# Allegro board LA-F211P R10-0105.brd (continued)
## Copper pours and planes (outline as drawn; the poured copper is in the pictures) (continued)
N25790 on BOTTOM (solid shape): 148.48,67.29 148.48,65.59 148.41,65.51 146.07,65.51 145.94,65.39 145.94,61.61 145.87,61.53 145.22,61.53 144.7,61 144.7,60 144.52,59.82 143.24,59.82 142.97,60.09 142.97,67.14 143.23,67.39 148.38,67.39
N25900 on BOTTOM (solid shape): 148,64.64 148,63.73 147.72,63.46 147.72,62.08 147.65,62.01 147.29,62.01 147.21,62.08 147.21,63.56 147.39,63.73 147.65,63.73 147.77,63.86 147.77,64.63 147.83,64.69 147.95,64.69
N25968 on BOTTOM (solid shape): 147.6,63.89 147.24,63.89 146.91,63.56 146.91,61.57 146.85,61.51 146.4,61.51 146.34,61.58 146.34,64.15 146.88,64.7 147.6,64.7
N29706 on BOTTOM (solid shape): 111.92,43.29 111.92,40.7 111.63,40.41 111.02,40.41 110.81,40.2 110.81,39.92 110.46,39.58 110.46,39.12 110.21,38.87 110.21,37.19 110.13,37.12 108.4,37.12 108.33,37.19 108.33,39.43 107.9,39.86 105.51,39.86 105.46,39.91 105.46,40.44 106.22,41.2 106.22,43.15 106.75,43.68 111.53,43.68
N54708 on BOTTOM (solid shape): 145.28,57.61 147.95,57.61 148.03,57.54 148.03,55.84 147.95,55.76 145.67,55.76 145.31,55.4 145.31,51.75 145.52,51.54 145.52,50.85 145.43,50.76 143.98,50.76 142.8,51.95 142.8,57.83 142.92,57.95 142.92,58.17 143.23,58.48 144.42,58.48
N54789 on TOP (solid shape): 115.27,43.35 115.28,43.35 115.38,43.25 115.38,40.58 115.18,40.37 112.51,40.37 112.35,40.53 112.35,43.07 112.78,43.5 115.12,43.5
N54789 on BOTTOM (solid shape): 119.47,43.62 119.47,40.52 119.16,40.2 117.9,40.2 117.71,40.01 117.71,38.49 117.07,37.85 117.07,36.23 116.99,36.15 115.24,36.15 115.19,36.2 115.19,38.72 114.96,38.94 113.1,38.94 113.01,38.86 112.35,38.86 112.3,38.91 112.3,43.03 113.1,43.82 119.26,43.82
N54830 on TOP (solid shape): 123.23,43.68 123.23,41.2 122.98,40.95 119.94,40.95 119.8,41.09 119.8,43.27 120.27,43.74 123.17,43.74
N54830 on BOTTOM (solid shape): 127.01,43.57 127.01,40.08 126.62,39.68 125.63,39.68 125.41,39.47 125.41,39.22 124.71,38.51 124.71,37.83 124.3,37.42 124.3,35.82 124.23,35.74 122.5,35.74 122.42,35.82 122.42,38.26 122.25,38.44 121.59,38.44 121.18,38.84 119.89,38.84 119.8,38.93 119.8,39.95 119.81,39.96 119.81,43.25 120.27,43.71 126.88,43.71
N19473637 on TOP (solid shape): 84.68,107.91 86.33,107.91 86.46,107.78 86.46,105.75 86.23,105.52 85.41,105.52 85.38,105.49 83.23,105.49 83.13,105.59 83.13,106.04 83.28,106.2 83.28,108.29 83.41,108.41 84.17,108.41
N46643804 on BOTTOM (solid shape): 114.37,37.9 114.37,37.06 113.59,37.06 113.59,37.7 113.36,37.93 112.35,37.93 112.3,37.98 112.3,38.55 112.39,38.64 113.64,38.64
N46645235 on BOTTOM (solid shape): 121.61,37.9 121.61,36.66 120.82,36.66 120.82,37.6 120.52,37.9 119.87,37.9 119.78,37.99 119.78,38.41 119.87,38.49 121.02,38.49
N46648066 on BOTTOM (solid shape): 147.55,54.9 147.55,53.98 147.04,53.47 147.04,52.13 146.94,52.03 146.58,52.03 146.45,52.15 146.45,53.6 146.83,53.98 147.16,53.98 147.32,54.13 147.32,54.9 147.37,54.95 147.49,54.95
N46648174 on BOTTOM (solid shape): 147.14,54.13 146.61,54.13 146.28,53.8 146.28,51.81 146.43,51.65 146.43,50.85 146.37,50.78 145.71,50.78 145.64,50.85 145.64,54.13 146.45,54.95 147.14,54.95
N46648510 on BOTTOM (solid shape): 107.32,39.5 107.32,39.01 107.51,38.82 107.51,38 106.73,38 106.7,38.03 106.7,38.46 106.19,38.98 105.49,38.98 105.44,39.02 105.44,39.53 105.62,39.71 107.12,39.71
N55155823 on TOP (solid shape): 62.46,99.9 62.46,99.52 62.96,99.02 63.6,99.02 63.85,98.76 63.85,98.13 64.04,97.94 64.04,96.95 63.82,96.73 62.17,96.73 61.82,97.08 61.82,99.9 61.95,100.03 62.33,100.03
N55155827 on TOP (solid shape): 63.99,96.37 64.59,95.62 65.33,96.23 66.09,96.23 66.19,96.14 66.19,95.33 66.32,95.2 66.32,94.54 66.22,94.44 64.82,94.44 64.67,94.29 63.47,94.29 63.32,94.44 60.21,94.44 59.85,94.8 59.85,96.3 59.97,96.41 63.95,96.41
N120361841 on BOTTOM (solid shape): 21.69,33.29 21.74,33.24 21.74,31.98 21.66,31.91 21.54,31.91 21.48,31.96 21.48,32.62 21.38,32.72 21.31,32.72 21.26,32.67 21.26,31.98 21.18,31.91 21.05,31.91 20.98,31.98 20.98,32.72 20.93,32.77 20.93,34.18 20.93,34.18 21.69,34.18
N122755391 on BOTTOM (solid shape): 84.16,27.45 84.16,27.21 84.34,27.03 85.26,27.03 85.32,26.98 85.32,26.09 85.06,25.84 82.14,25.84 81.99,25.99 81.99,27.31 82.17,27.49 84.12,27.49
N122912247 on TOP (solid shape): 112.77,29.93 112.77,28.71 112.99,28.49 112.99,27.67 113.24,27.43 113.24,26.7 113.17,26.63 111.76,26.63 111.65,26.73 111.65,29.99 111.8,30.13 112.57,30.13
N125857121 on BOTTOM (solid shape): 65.76,89.9 65.76,87.97 65.38,87.59 63.23,87.59 63.11,87.71 63.11,89.56 63.27,89.72 64.16,89.72 64.16,89.99 64.27,90.11 65.55,90.11
N125861425 on TOP (solid shape): 149.51,103.59 149.85,103.47 150.03,103.16 150.03,102.49 149.96,102.31 149.83,102.16 149.64,101.98 146.9,101.98 146.88,102 146.88,103.35 146.96,103.44 147.65,103.44 147.8,103.59
N127291517 on BOTTOM (solid shape): 56.42,102.13 56.42,101.24 56.23,101.05 55.44,101.05 55.06,101.42 54.08,101.42 53.95,101.56 53.95,102.06 54.07,102.19 56.36,102.19
N132640228 on BOTTOM (solid shape): 163.93,13.17 163.93,12.47 163.85,12.39 163.02,12.39 162.76,12.13 162.76,11.49 162.68,11.41 161.94,11.41 161.88,11.47 161.88,12.42 162.03,12.57 162.16,12.57 162.33,12.74 162.33,12.87 162.68,13.22 163.88,13.22
N132938389 on BOTTOM (solid shape): 60.02,80.78 59.97,80.73 59.08,80.73 58.92,80.88 57.71,80.88 57.71,81.13 57.78,81.21 59.1,81.21 59.36,81.46 60.02,81.46
N132946479 on BOTTOM (solid shape): 13.43,23.58 12.93,23.58 12.8,23.7 11.27,23.7 11.15,23.83 11.15,23.96 11.27,24.09 13.43,24.09
N132946567 on BOTTOM (solid shape): 13.94,24.72 14.58,24.72 14.7,24.59 14.7,23.83 14.58,23.7 13.94,23.7 13.81,23.83 13.81,24.09 13.56,24.34 10.89,24.34 10.89,23.96 10.77,23.83 10.64,23.83 10.51,23.96 10.51,24.59 11.02,25.1 13.56,25.1
N132946609 on BOTTOM (solid shape): 59.86,81.82 59.84,81.79 59.77,81.79 59.75,81.81 59.19,81.81 58.85,81.46 57.55,81.46 57.45,81.36 57.45,81.06 57.27,80.88 57.04,80.88 56.97,80.96 56.97,81.87 57.67,82.57 59.12,82.57 59.25,82.71 59.86,82.71
N133127797 on TOP (solid shape): 68.42,101.49 67.79,100.86 66.07,100.86 66.01,100.92 66.01,101.94 66.14,102.06 68.42,102.06
N133127913 on TOP (solid shape): 65.69,105.11 64.8,104.22 64.55,104.22 64.55,105.05 65,105.49 65,106.19 65.12,106.32 65.69,106.32
N133127941 on TOP (solid shape): 66.96,105.07 65.36,103.47 64.61,103.47 64.55,103.53 64.55,103.97 64.61,104.03 64.93,104.03 66.07,105.17 66.07,105.75 66.96,105.75
N137153201 on BOTTOM (solid shape): 47.02,70.5 47.02,69.02 47.09,68.95 47.09,67.77 46.83,67.52 46.33,67.52 46.2,67.65 46.2,68.71 46.2,68.72 46.21,68.89 46.1,69.02 46.07,69.04 46.07,69.81 45.95,69.93 45.31,69.93 45.18,70.06 45.18,70.57 45.31,70.69 46.83,70.69
N140304666 on TOP (solid shape): 60.17,52.09 60.17,50.12 60.04,49.99 59.22,49.99 59.15,50.06 59.15,51.07 58.39,51.83 58.39,52.47 58.52,52.6 59.66,52.6
N142919801 on BOTTOM (solid shape): 82.69,22.27 84.12,22.27 84.17,22.22 84.17,20.77 83.97,20.57 81.46,20.57 81.31,20.73 81.31,21.38 81.12,21.56 81.12,22.43 81.25,22.56 82.39,22.56
N143012284 on BOTTOM (solid shape): 153.51,5.29 153.51,3.51 152.57,2.57 152.56,2.57 152.51,2.51 152.13,2.51 152.07,2.58 151.75,2.58 151.65,2.48 151.03,2.48 151,2.44 151,1.79 150.81,1.61 147.93,1.61 147.8,1.73 147.8,2.43 148.5,2.43 148.75,2.69 148.75,2.94 148.5,3.19 147.8,3.19 147.8,3.77 147.93,3.89 148.75,3.89 148.93,4.07 148.93,4.07 150.47,5.61 153.2,5.61
N146334871 on BOTTOM (solid shape): 93.95,28.56 93.95,27.77 93.85,27.67 91.54,27.67 91.53,27.68 91.53,28.62 91.56,28.66 93.85,28.66
N146336831 on TOP (solid shape): 27.75,29.98 27.75,28.53 27.67,28.45 26.84,28.45 26.67,28.63 25.4,28.63 25.29,28.73 25.29,28.83 25.37,28.91 26.06,28.91 26.13,28.99 26.13,29.09 26.08,29.14 25.4,29.14 25.29,29.24 25.29,29.5 25.45,29.65 26.46,29.65 26.87,30.05 27.67,30.05
N146979809 on TOP: 68.07,87.68 69.36,87.68 69.86,88.19 69.86,89.22 69.31,89.77 68.41,89.77 68.34,89.71 68.34,89.12 68.01,88.79 68.01,87.74
N146979833 on TOP: 65.21,87.7 64.9,88 64.9,88.66 65.33,89.09 65.33,89.71 65.42,89.8 66.23,89.8 66.34,89.69 66.34,89.12 66.66,88.8 66.66,87.76 66.59,87.7
N146979907 on BOTTOM (solid shape): 60.73,72.52 60.73,70.81 60.65,70.73 59.62,70.73 59.43,70.55 57.35,70.55 57.29,70.61 57.29,71.28 57.4,71.39 58.36,71.39 58.7,71.73 59.6,71.73 59.7,71.83 59.7,72.58 59.77,72.65 60.6,72.65
N148592439 on BOTTOM (solid shape): 88.11,34.09 88.11,32.38 87.88,32.15 86.99,32.15 86.93,32.21 86.93,32.91 87.21,33.19 87.44,33.19 87.75,33.5 87.75,34.1 87.84,34.19 88.01,34.19
N148592442 on BOTTOM (solid shape): 87.95,31.5 87.95,30.8 87.87,30.72 85.51,30.72 85.41,30.82 85.41,31.47 85.5,31.56 87.89,31.56
N148592463 on BOTTOM (solid shape): 87.09,34.12 87.09,33.24 86.6,32.75 86.6,32.21 86.5,32.11 85.47,32.11 85.39,32.19 85.39,33.03 85.54,33.17 86.37,33.17 86.75,33.55 86.75,34.11 86.85,34.21 87.01,34.21
N148593135 on BOTTOM (solid shape): 89.08,34.11 89.08,33.13 89.32,32.88 89.32,32.26 89.72,31.87 90.27,31.87 90.57,31.58 90.57,30.82 90.46,30.71 89.5,30.71 89.37,30.84 89.37,31.52 89.18,31.72 88.39,31.72 88.29,31.82 88.29,32.99 88.76,33.46 88.76,34.11 88.85,34.2 88.99,34.2
N148597432 on BOTTOM (solid shape): 70.78,34.15 70.78,32.35 70.64,32.2 69.49,32.2 69.47,32.22 69.47,32.86 69.64,33.03 69.98,33.03 70.44,33.48 70.44,34.14 70.49,34.2 70.73,34.2
N148597434 on BOTTOM (solid shape): 70.49,31.54 70.49,30.77 70.38,30.66 68.19,30.66 68.1,30.75 68.1,31.54 68.21,31.65 70.38,31.65
N148597440 on BOTTOM (solid shape): 69.78,34.13 69.78,33.36 69.21,32.79 69.21,32.28 69.1,32.17 68.19,32.17 68.16,32.2 68.16,32.91 68.28,33.03 68.93,33.03 69.44,33.54 69.44,34.13 69.5,34.2 69.72,34.2
N148597468 on BOTTOM (solid shape): 71.77,34.13 71.77,33.27 72.04,33 72.04,32.25 72.31,31.99 73.14,31.99 73.33,31.8 73.33,30.79 73.25,30.71 72.17,30.71 72.09,30.78 72.09,31.54 71.97,31.66 71.07,31.66 70.96,31.78 70.96,32.97 71.45,33.47 71.45,33.85 71.45,33.85 71.45,34.15 71.5,34.2 71.7,34.2
N148599110 on BOTTOM (solid shape): 79.36,34.12 79.36,32.41 79.13,32.17 78.24,32.17 78.18,32.23 78.18,32.85 78.54,33.21 78.69,33.21 79,33.53 79,34.13 79.09,34.22 79.26,34.22
N148599112 on BOTTOM (solid shape): 79.19,31.54 79.19,30.82 79.09,30.71 76.9,30.71 76.78,30.83 76.78,31.54 76.84,31.6 79.14,31.6
N148599118 on BOTTOM (solid shape): 78.34,34.14 78.34,33.21 77.85,32.72 77.85,32.23 77.75,32.13 76.8,32.13 76.77,32.16 76.77,33.09 76.88,33.2 77.66,33.2 78,33.54 78,34.13 78.1,34.23 78.26,34.23
N148599146 on BOTTOM (solid shape): 80.33,34.14 80.33,33.15 80.57,32.91 80.57,32.16 80.83,31.9 81.52,31.9 81.82,31.6 81.82,30.84 81.71,30.74 80.75,30.74 80.62,30.87 80.62,31.51 80.39,31.74 79.64,31.74 79.54,31.85 79.54,33.01 80.01,33.48 80.01,34.13 80.1,34.22 80.24,34.22
N148600854 on BOTTOM (solid shape): 96.95,34.11 96.95,33.26 96.58,32.89 96.58,32.24 96.45,32.11 95.59,32.11 95.53,32.17 95.53,32.84 95.89,33.2 96.05,33.2 96.05,33.2 96.28,33.2 96.59,33.51 96.59,34.12 96.68,34.21 96.85,34.21
N148600856 on BOTTOM (solid shape): 96.52,31.44 96.52,30.79 96.44,30.71 94.11,30.71 94.04,30.78 94.04,31.41 94.13,31.5 96.47,31.5
N148600862 on BOTTOM (solid shape): 95.93,34.13 95.93,33.41 95.38,32.86 95.38,32.16 95.34,32.12 94.16,32.12 94.11,32.17 94.11,33.03 94.26,33.18 95.21,33.18 95.59,33.56 95.59,34.12 95.69,34.22 95.85,34.22
N148600909 on BOTTOM (solid shape): 97.91,34.13 97.91,32.15 98.18,31.89 98.99,31.89 99.1,31.77 99.1,30.8 99.03,30.72 98,30.72 97.95,30.78 97.95,31.38 97.68,31.65 97.11,31.65 96.83,31.92 96.83,32.86 96.97,33 97.13,33 97.6,33.47 97.6,34.12 97.69,34.21 97.83,34.21
N150849033 on TOP (solid shape): 158.36,21.8 158.36,20.87 157.46,19.97 157.46,19.52 157.4,19.45 156.81,19.45 156.28,19.99 156.28,20.22 156.22,20.28 156.22,21.38 156.26,21.42 156.97,21.42 157.6,22.05 158.11,22.05
N151224429 on TOP (solid shape): 62.15,75.24 62.15,74.76 62.55,74.37 62.55,73.53 61.91,72.88 59.92,72.88 59.74,73.06 59.74,74.04 59.8,74.1 61.27,74.1 61.59,74.42 61.59,75.25 61.69,75.34 62.05,75.34
N151224640 on TOP (solid shape): 59.61,75.27 59.61,73.39 59.19,72.97 56.04,72.97 55.91,73.1 55.91,73.81 56.27,74.17 58.67,74.17 59.1,74.59 59.1,75.23 59.2,75.33 59.55,75.33
N151224855 on TOP (solid shape): 50.28,54.76 50.28,53.46 50.09,53.27 49.3,53.27 49.29,53.28 48.69,53.28 48.55,53.42 48.55,54.6 49.02,55.07 49.97,55.07
N153659070 on BOTTOM (solid shape): 5.03,9.2 6.56,9.2 6.72,9.04 6.72,7.98 6.66,7.91 4.75,7.91 4.11,8.55 3.36,8.55 3.16,8.75 3.16,9.75 3.33,9.92 4.32,9.92
N154411599 on TOP (solid shape): 120.01,20.58 120.01,19.45 119.9,19.34 118.68,19.34 118.59,19.43 116.64,19.43 116.56,19.51 116.56,20.48 116.73,20.66 119.94,20.66
N154411647 on TOP (solid shape): 121.89,20.07 121.89,19.46 121.74,19.31 120.22,19.31 120.12,19.42 120.12,20.17 120.22,20.28 121.69,20.28
N154450732 on TOP (solid shape): 142.56,85.5 142.56,81.97 142.42,81.83 141.88,81.83 141.75,81.96 141.75,85.46 141.83,85.54 142.52,85.54
N154450766 on TOP (solid shape): 141.54,82.36 141.54,81.77 141.16,81.39 139.94,81.39 139.86,81.47 139.86,82.13 139.98,82.26 140.77,82.26 140.91,82.4 141.5,82.4

Small or netless copper shapes (teardrops, artwork), in the pictures only: 47 on TOP, 40 on BOTTOM, 4 on IN1, 128 on GND2, 270 on GND3, 1 on GND4

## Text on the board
Ref Des/Silkscreen Bottom: H5 | H27 | S1 | H4 | S2 | OFF | ON
User.Comments: LAF211P | 2019-01-05 | 2018-01-05 | DAZ10 | crazy | 1.0(A00)
Ref Des/Silkscreen Top: S3 | H52 | H51
GND4: GND4
XSECTION_CHART: * | L1: TOP | L2: GND1 | L3: IN1 | L4: GND2 | L5: IN2 | L6: VCC | L7: GND3 | L8: IN3 | L9: GND4 | L10: BOTTOM | DESIGN CROSS SECTION CHART | ___________________________ | TOTAL THICKNESS 39.86 MIL | 1-10 | 1-2 | 1-3 | 1-4 | 2-4 | 2-3 | 3-4 | 4-7 | 7-8 | 7-10 | 7-9 | 8-10 | 8-9 | 9-10
User.43: Width/space | 3.8 | 4.4 / 6 | 7 / 4.2 | 40 ohm | 72 ohm
User.44: FIGURE | SIZE | 8.0 | 16.0 | 26.0 | 47.0 | 63.0 | 91.0 | 130.0 | 138.0 | 31.0 | 33.0 | 37.0 | 39.0 | 43.0 | 106.0 | 154.0 | 236.0 | 47.0x16.0 | 49.0x26.0 | 57.0x24.0 | 63.0x24.0 | 71.0x51.0 | 37.0x31.0 | 59.0x43.0 | DRILL CHART: TOP to BOTTOM | ALL UNITS ARE IN MILS | TOLERANCE | +3.0/-3.0 | +2.0/-2.0 | PLATED | NON-PLATED | QTY | 2310 | 24 | 2 | 1 | 5 | 4
User.45: FIGURE | SIZE | 4.0 | 8.0 | DRILL CHART: TOP to GND1 | ALL UNITS ARE IN MILS | DRILL CHART: TOP to IN1 | DRILL CHART: TOP to GND2 | DRILL CHART: GND1 to IN1 | DRILL CHART: GND1 to GND2 | DRILL CHART: IN1 to GND2 | DRILL CHART: GND2 to GND3 | DRILL CHART: GND3 to IN3 | DRILL CHART: GND3 to GND4 | DRILL CHART: GND3 to BOTTOM | TOLERANCE | +1.0/-1.0 | +3.0/-3.0 | PLATED | QTY | 943 | 742 | 2203 | 420 | 518 | 881 | 3485 | 1399 | 209 | 2482 | DRILL CHART: IN3 to GND4 | DRILL CHART: IN3 to BOTTOM | DRILL CHART: GND4 to BOTTOM | 1014 | 1022 | 1714
